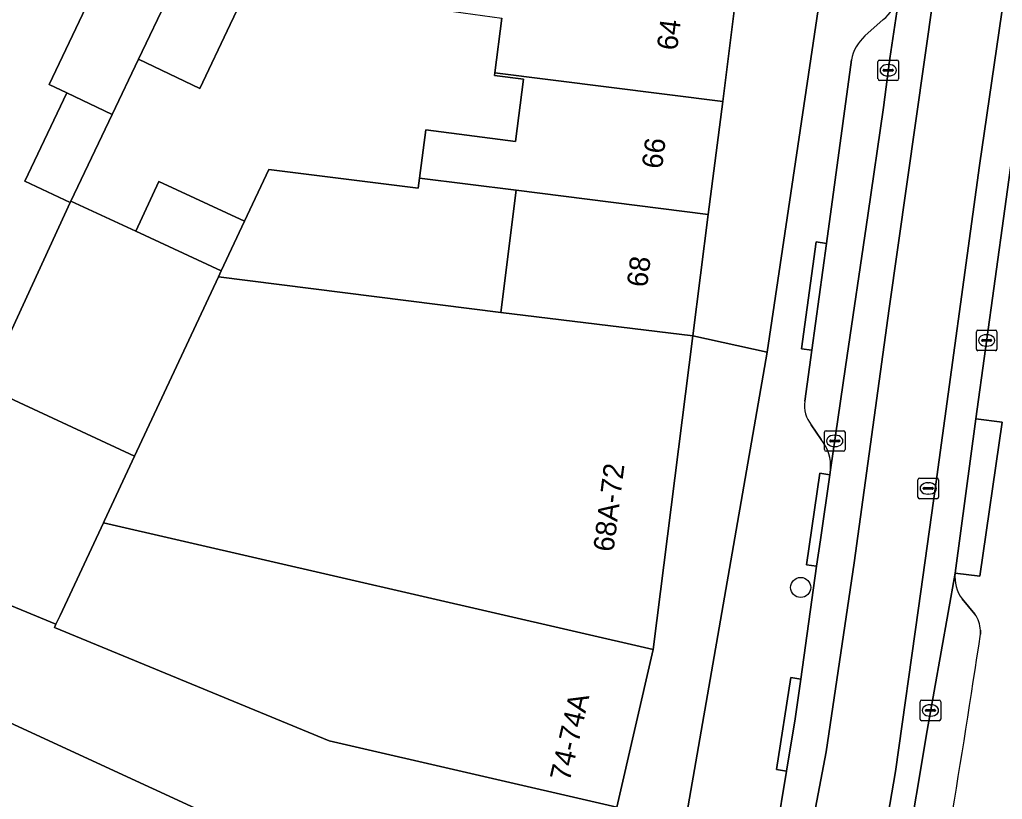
# Model space of a CAD drawing. Extents: x 160349 to 161355, y 381727 to 382854.
# Drawn here: x 160838.74 to 160886.69, y 382389.67 to 382427.71 of the extents above; entities that cross this region are included whole.
import ezdxf

# ---------------------------------------------------------------- set-up
doc = ezdxf.new("R2010")
doc.units = 0
for name, color, linetype in [('IMGEO_Boom', 7, 'Continuous'), ('IMGEO_Erf', 7, 'Continuous'), ('IMGEO_Kolk', 7, 'Continuous'), ('IMGEO_Pand', 7, 'Continuous'), ('IMGEO_Pand_nummerreeks', 7, 'Continuous'), ('IMGEO_Parkeervlak_open', 7, 'Continuous'), ('IMGEO_Rijbaan_lokaal_gesloten', 7, 'Continuous'), ('IMGEO_Rioolput', 7, 'Continuous'), ('IMGEO_Voetpad_open', 7, 'Continuous')]:
    doc.layers.add(name, color=color, linetype=linetype)

msp = doc.modelspace()

# ---------------------------------------------------------------- linework, layer by layer
at = {"layer": 'IMGEO_Boom'}
msp.add_circle((160876.853, 382400.008), 0.489, dxfattribs=at)
at = {"layer": 'IMGEO_Erf'}
for points in [[(160838.99, 382419.837), (160841.034, 382424.136), (160840.178, 382424.543), (160844.715, 382434.085), (160840.65, 382435.888), (160842.793, 382440.716), (160844.328, 382440.034), (160845.356, 382442.352), (160847.503, 382446.867), (160844.97, 382447.935), (160842.8, 382443.431), (160841.079, 382439.861), (160841.402, 382439.699), (160836.819, 382430.561)], [(160850.819, 382431.268), (160849.014, 382427.472), (160847.534, 382424.359), (160844.542, 382425.78), (160843.259, 382423.078), (160841.24, 382418.852), (160844.41, 382417.386), (160845.531, 382419.811), (160849.711, 382417.879), (160850.893, 382420.407), (160858.191, 382419.481), (160858.255, 382419.983), (160858.552, 382422.327), (160862.934, 382421.771), (160863.319, 382424.806), (160861.918, 382424.983), (160861.935, 382425.121), (160862.273, 382427.785)], [(160833.248, 382401.214), (160840.51, 382398.208), (160840.713, 382398.638), (160842.823, 382403.154), (160842.875, 382403.269), (160844.341, 382406.407), (160837.05, 382409.79), (160841.207, 382418.783), (160838.99, 382419.837)], [(160852.386, 382386.901), (160831.107, 382396.697), (160827.103, 382388.219)]]:
    msp.add_lwpolyline(points, dxfattribs=at)
at = {"layer": 'IMGEO_Kolk'}
for p, q in [((160880.626, 382424.815), (160880.626, 382425.667)), ((160880.701, 382425.741), (160881.553, 382425.741)), ((160881.114, 382425.521), (160881.139, 382425.521)), ((160881.627, 382425.667), (160881.627, 382424.815)), ((160880.885, 382425.235), (160880.885, 382425.247)), ((160881.323, 382425.198), (160880.925, 382425.198)), ((160880.928, 382425.284), (160881.326, 382425.284)), ((160881.369, 382425.247), (160881.369, 382425.235)), ((160881.553, 382424.741), (160880.701, 382424.741)), ((160881.137, 382424.961), (160881.112, 382424.961)), ((160885.503, 382412.56), (160886.355, 382412.56)), ((160885.428, 382411.634), (160885.428, 382412.486)), ((160885.687, 382412.054), (160885.687, 382412.066)), ((160885.73, 382412.103), (160886.128, 382412.103)), ((160885.916, 382412.34), (160885.941, 382412.34)), ((160886.171, 382412.066), (160886.171, 382412.054)), ((160886.429, 382412.486), (160886.429, 382411.634)), ((160886.355, 382411.56), (160885.503, 382411.56)), ((160886.125, 382412.017), (160885.727, 382412.017)), ((160885.939, 382411.78), (160885.914, 382411.78)), ((160878.015, 382406.73), (160878.015, 382407.582)), ((160878.09, 382407.656), (160878.942, 382407.656)), ((160878.503, 382407.436), (160878.528, 382407.436)), ((160879.016, 382407.582), (160879.016, 382406.73)), ((160878.274, 382407.15), (160878.274, 382407.162)), ((160878.712, 382407.113), (160878.314, 382407.113)), ((160878.317, 382407.199), (160878.715, 382407.199)), ((160878.526, 382406.876), (160878.501, 382406.876)), ((160878.758, 382407.162), (160878.758, 382407.15)), ((160878.942, 382406.656), (160878.09, 382406.656)), ((160882.684, 382393.58), (160882.684, 382394.432)), ((160882.759, 382394.506), (160883.611, 382394.506)), ((160883.172, 382394.286), (160883.197, 382394.286)), ((160883.685, 382394.432), (160883.685, 382393.58)), ((160882.943, 382394), (160882.943, 382394.012)), ((160883.381, 382393.963), (160882.983, 382393.963)), ((160882.986, 382394.049), (160883.384, 382394.049)), ((160883.427, 382394.012), (160883.427, 382394)), ((160883.611, 382393.506), (160882.759, 382393.506)), ((160883.195, 382393.726), (160883.17, 382393.726))]:
    msp.add_line(p, q, dxfattribs=at)
for points in [[(160880.626, 382424.815), (160880.626, 382425.667)], [(160880.701, 382425.741), (160881.553, 382425.741)], [(160881.627, 382425.667), (160881.627, 382424.815)], [(160881.553, 382424.741), (160880.701, 382424.741)], [(160885.503, 382412.56), (160886.355, 382412.56)], [(160885.428, 382411.634), (160885.428, 382412.486)], [(160886.429, 382412.486), (160886.429, 382411.634)], [(160886.355, 382411.56), (160885.503, 382411.56)], [(160878.015, 382406.73), (160878.015, 382407.582)], [(160878.09, 382407.656), (160878.942, 382407.656)], [(160879.016, 382407.582), (160879.016, 382406.73)], [(160878.942, 382406.656), (160878.09, 382406.656)], [(160882.684, 382393.58), (160882.684, 382394.432)], [(160882.759, 382394.506), (160883.611, 382394.506)], [(160883.685, 382394.432), (160883.685, 382393.58)], [(160883.611, 382393.506), (160882.759, 382393.506)]]:
    msp.add_lwpolyline(points, dxfattribs=at)
for centre, radius, start, end in [((160880.703, 382425.665), 0.0765, 91.552, 178.448), ((160880.703, 382425.665), 0.0765, 91.552, 178.448), ((160881.551, 382425.665), 0.0765, 1.552, 88.448), ((160881.551, 382425.665), 0.0765, 1.552, 88.448), ((160880.925, 382425.244), 0.0403, 85.8775, 175.7526), ((160880.922, 382425.234), 0.0366, 178.938, 274.7102), ((160881.326, 382425.241), 0.043, 264.8664, 352.4533), ((160881.33, 382425.246), 0.0386, 1.7309, 96.639), ((160880.703, 382424.817), 0.0765, 181.552, 268.448), ((160880.703, 382424.817), 0.0765, 181.552, 268.448), ((160881.551, 382424.817), 0.0765, 271.552, 358.448), ((160881.551, 382424.817), 0.0765, 271.552, 358.448), ((160885.505, 382412.484), 0.0765, 91.552, 178.448), ((160885.505, 382412.484), 0.0765, 91.552, 178.448), ((160886.353, 382412.484), 0.0765, 1.552, 88.448), ((160886.353, 382412.484), 0.0765, 1.552, 88.448), ((160885.727, 382412.063), 0.0403, 85.8775, 175.7526), ((160885.724, 382412.053), 0.0366, 178.938, 274.7102), ((160886.128, 382412.06), 0.043, 264.8664, 352.4533), ((160886.132, 382412.065), 0.0386, 1.7309, 96.639), ((160885.505, 382411.636), 0.0765, 181.552, 268.448), ((160885.505, 382411.636), 0.0765, 181.552, 268.448), ((160886.353, 382411.636), 0.0765, 271.552, 358.448), ((160886.353, 382411.636), 0.0765, 271.552, 358.448), ((160878.092, 382407.58), 0.0765, 91.552, 178.448), ((160878.092, 382407.58), 0.0765, 91.552, 178.448), ((160878.94, 382407.58), 0.0765, 1.552, 88.448), ((160878.94, 382407.58), 0.0765, 1.552, 88.448), ((160878.314, 382407.159), 0.0403, 85.8775, 175.7526), ((160878.311, 382407.149), 0.0366, 178.938, 274.7102), ((160878.715, 382407.156), 0.043, 264.8664, 352.4533), ((160878.719, 382407.161), 0.0386, 1.7309, 96.639), ((160878.092, 382406.732), 0.0765, 181.552, 268.448), ((160878.092, 382406.732), 0.0765, 181.552, 268.448), ((160878.94, 382406.732), 0.0765, 271.552, 358.448), ((160878.94, 382406.732), 0.0765, 271.552, 358.448), ((160882.761, 382394.43), 0.0765, 91.552, 178.448), ((160882.761, 382394.43), 0.0765, 91.552, 178.448), ((160883.609, 382394.43), 0.0765, 1.552, 88.448), ((160883.609, 382394.43), 0.0765, 1.552, 88.448), ((160882.983, 382394.009), 0.0403, 85.8775, 175.7526), ((160882.98, 382393.999), 0.0366, 178.938, 274.7102), ((160883.384, 382394.006), 0.043, 264.8664, 352.4533), ((160883.388, 382394.011), 0.0386, 1.7309, 96.639), ((160882.761, 382393.582), 0.0765, 181.552, 268.448), ((160882.761, 382393.582), 0.0765, 181.552, 268.448), ((160883.609, 382393.582), 0.0765, 271.552, 358.448), ((160883.609, 382393.582), 0.0765, 271.552, 358.448)]:
    msp.add_arc(centre, radius, start, end, dxfattribs=at)
for centre, major_axis, ratio, start_param, end_param in [((160881.113, 382425.241), (-0.387, 0.002), 0.722429, 4.712389, 7.853982), ((160881.138, 382425.241), (-0.39, 0.002), 0.717154, 1.570796, 4.712389), ((160885.915, 382412.06), (-0.387, 0.002), 0.722429, 4.712389, 7.853982), ((160885.94, 382412.06), (-0.39, 0.002), 0.717154, 1.570796, 4.712389), ((160878.502, 382407.156), (-0.387, 0.002), 0.722429, 4.712389, 7.853982), ((160878.527, 382407.156), (-0.39, 0.002), 0.717154, 1.570796, 4.712389), ((160883.171, 382394.006), (-0.387, 0.002), 0.722429, 4.712389, 7.853982), ((160883.196, 382394.006), (-0.39, 0.002), 0.717154, 1.570796, 4.712389)]:
    msp.add_ellipse(centre, major_axis=major_axis, ratio=ratio, start_param=start_param, end_param=end_param, dxfattribs=at)
at = {"layer": 'IMGEO_Pand'}
for points in [[(160853.11, 382443.819), (160850.234, 382445.187), (160850.382, 382445.498), (160847.503, 382446.867), (160845.356, 382442.352), (160844.328, 382440.034), (160842.793, 382440.716), (160840.65, 382435.888), (160844.715, 382434.085), (160840.178, 382424.543), (160841.034, 382424.136), (160843.259, 382423.078), (160844.542, 382425.78), (160846.022, 382428.895)], [(160857.557, 382436.557), (160859.705, 382441.072), (160854.36, 382443.615), (160854.209, 382443.296), (160853.11, 382443.819), (160846.022, 382428.895), (160844.542, 382425.78), (160847.534, 382424.359), (160849.014, 382427.472), (160850.819, 382431.268), (160855.018, 382429.271), (160856.844, 382433.112), (160856.069, 382433.471)], [(160873.776, 382429.466), (160857.365, 382431.653), (160856.39, 382429.554), (160858.62, 382429.248), (160858.489, 382428.298), (160862.273, 382427.785), (160861.935, 382425.121), (160873.046, 382423.712)], [(160861.935, 382425.121), (160861.918, 382424.983), (160863.319, 382424.806), (160862.934, 382421.771), (160858.552, 382422.327), (160858.255, 382419.983), (160862.976, 382419.385), (160872.346, 382418.197), (160873.046, 382423.712)], [(160843.259, 382423.078), (160841.034, 382424.136), (160838.99, 382419.837), (160841.207, 382418.783), (160841.24, 382418.852)], [(160848.579, 382415.459), (160848.442, 382415.167), (160862.22, 382413.42), (160862.976, 382419.385), (160858.255, 382419.983), (160858.191, 382419.481), (160850.893, 382420.407), (160849.711, 382417.879)], [(160848.579, 382415.459), (160849.711, 382417.879), (160845.531, 382419.811), (160844.41, 382417.386)], [(160872.346, 382418.197), (160862.976, 382419.385), (160862.22, 382413.42), (160871.595, 382412.277)], [(160848.442, 382415.167), (160848.579, 382415.459), (160844.41, 382417.386), (160841.24, 382418.852), (160841.207, 382418.783), (160837.05, 382409.79), (160844.341, 382406.407)], [(160844.341, 382406.407), (160842.875, 382403.269), (160842.823, 382403.154), (160869.655, 382396.98), (160871.595, 382412.277), (160862.22, 382413.42), (160848.442, 382415.167)], [(160842.823, 382403.154), (160840.713, 382398.638), (160840.51, 382398.208), (160840.441, 382398.06), (160853.85, 382392.531), (160867.882, 382389.295), (160869.655, 382396.98)], [(160857.877, 382385.543), (160866.575, 382383.629), (160867.882, 382389.295), (160853.85, 382392.531), (160840.441, 382398.06), (160840.51, 382398.208), (160833.248, 382401.214), (160831.107, 382396.697), (160852.386, 382386.901), (160856.493, 382385.863)]]:
    msp.add_lwpolyline(points, close=True, dxfattribs=at)
at = {"layer": 'IMGEO_Parkeervlak_open'}
for points in [[(160878.312, 382405.748), (160879.045, 382410.779), (160880.13, 382418.151), (160880.898, 382423.426), (160881.202, 382425.818), (160881.647, 382428.757)], [(160880.886, 382427.71), (160879.99, 382426.916)], [(160879.326, 382425.742), (160878.106, 382416.795), (160877.395, 382411.585), (160877.055, 382409.091)], [(160877.369, 382407.938), (160877.857, 382407.231)], [(160884.389, 382400.707), (160883.026, 382393.026), (160880.919, 382380.402), (160878.135, 382368.511), (160876.154, 382361.855), (160875.162, 382358.523), (160869.629, 382343.884)], [(160885.353, 382398.704), (160884.727, 382399.448)], [(160885.633, 382397.726), (160885.626, 382397.917)]]:
    msp.add_lwpolyline(points, dxfattribs=at)
for centre, radius, start, end in [((160878.953, 382429.915), 2.932, 311.2385, 336.7393), ((160881.385, 382425.353), 2.095, 131.7305, 169.2856), ((160878.526, 382408.872), 1.487, 171.5487, 218.9195), ((160876.137, 382405.892), 2.18, 356.2113, 37.9018), ((160886.232, 382400.527), 1.851, 174.4143, 215.641), ((160884.197, 382397.862), 1.43, 2.2007, 36.0612), ((160242.151, 382494.956), 650.786, 349.758294, 351.407572)]:
    msp.add_arc(centre, radius, start, end, dxfattribs=at)
at = {"layer": 'IMGEO_Rijbaan_lokaal_gesloten'}
for points in [[(160885.854, 382456.356), (160885.223, 382452.521), (160884.594, 382448.404), (160881.688, 382429.028), (160881.647, 382428.757), (160881.202, 382425.818), (160880.898, 382423.426), (160880.13, 382418.151), (160879.045, 382410.779), (160878.312, 382405.748), (160878.277, 382405.504), (160877.814, 382402.326), (160877.633, 382401.041), (160876.858, 382395.532), (160876.585, 382393.594), (160876.163, 382391.049), (160875.148, 382384.925), (160874.712, 382382.293), (160873.06, 382374.355)], [(160870.943, 382366.742), (160870.039, 382363.675), (160871.535, 382363.229), (160871.549, 382363.225), (160872.864, 382367.516), (160875.093, 382376.203), (160878.093, 382391.995), (160879.468, 382401.203), (160881.177, 382413.62), (160883.781, 382431.953), (160885.906, 382445.891), (160887.065, 382452.22)], [(160887.065, 382452.22), (160885.906, 382445.891), (160883.781, 382431.953), (160881.177, 382413.62), (160879.468, 382401.203), (160878.093, 382391.995), (160875.093, 382376.203), (160872.864, 382367.516), (160871.549, 382363.225), (160874.812, 382362.252), (160876.305, 382367.268), (160878.01, 382373.759), (160879.223, 382378.677), (160880.076, 382382.874), (160881.485, 382391.022), (160882.6, 382398.989), (160883.453, 382405.054), (160885.584, 382420.595), (160889.059, 382444.497), (160890.141, 382451.415)], [(160889.059, 382444.497), (160885.584, 382420.595), (160883.453, 382405.054), (160882.6, 382398.989), (160881.485, 382391.022), (160880.076, 382382.874), (160879.223, 382378.677), (160878.01, 382373.759), (160876.305, 382367.268), (160874.812, 382362.252), (160876.154, 382361.855), (160878.135, 382368.511), (160880.919, 382380.402), (160883.026, 382393.026), (160884.389, 382400.707), (160885.402, 382408.232), (160887.753, 382425.309)]]:
    msp.add_lwpolyline(points, dxfattribs=at)
at = {"layer": 'IMGEO_Rioolput'}
for p, q in [((160882.652, 382405.338), (160883.504, 382405.338)), ((160882.577, 382404.412), (160882.577, 382405.264)), ((160882.836, 382404.832), (160882.836, 382404.844)), ((160882.879, 382404.881), (160883.277, 382404.881)), ((160883.065, 382405.118), (160883.09, 382405.118)), ((160883.32, 382404.844), (160883.32, 382404.832)), ((160883.578, 382405.264), (160883.578, 382404.412)), ((160883.274, 382404.795), (160882.876, 382404.795)), ((160883.088, 382404.558), (160883.063, 382404.558)), ((160883.504, 382404.338), (160882.652, 382404.338))]:
    msp.add_line(p, q, dxfattribs=at)
for points in [[(160882.652, 382405.338), (160883.504, 382405.338)], [(160882.577, 382404.412), (160882.577, 382405.264)], [(160883.578, 382405.264), (160883.578, 382404.412)], [(160883.504, 382404.338), (160882.652, 382404.338)]]:
    msp.add_lwpolyline(points, dxfattribs=at)
for centre, radius, start, end in [((160882.654, 382405.262), 0.0765, 91.552, 178.448), ((160882.654, 382405.262), 0.0765, 91.552, 178.448), ((160883.502, 382405.262), 0.0765, 1.552, 88.448), ((160883.502, 382405.262), 0.0765, 1.552, 88.448), ((160882.876, 382404.841), 0.0403, 85.8775, 175.7526), ((160883.281, 382404.843), 0.0386, 1.7309, 96.639), ((160882.654, 382404.414), 0.0765, 181.552, 268.448), ((160882.654, 382404.414), 0.0765, 181.552, 268.448), ((160882.873, 382404.831), 0.0366, 178.938, 274.7102), ((160883.277, 382404.838), 0.043, 264.8664, 352.4533), ((160883.502, 382404.414), 0.0765, 271.552, 358.448), ((160883.502, 382404.414), 0.0765, 271.552, 358.448)]:
    msp.add_arc(centre, radius, start, end, dxfattribs=at)
for centre, major_axis, ratio, start_param, end_param in [((160883.064, 382404.838), (-0.387, 0.002), 0.722429, 4.712389, 7.853982), ((160883.089, 382404.838), (-0.39, 0.002), 0.717154, 1.570796, 4.712389)]:
    msp.add_ellipse(centre, major_axis=major_axis, ratio=ratio, start_param=start_param, end_param=end_param, dxfattribs=at)
at = {"layer": 'IMGEO_Voetpad_open'}
for points in [[(160877.876, 382429.319), (160878.34, 382432.421), (160874.377, 382434.208), (160874.342, 382433.93), (160877.67, 382432.369), (160877.181, 382428.975), (160873.776, 382429.466), (160873.046, 382423.712), (160872.346, 382418.197), (160871.595, 382412.277), (160875.211, 382411.49)], [(160878.106, 382416.795), (160877.612, 382416.866), (160876.901, 382411.656), (160877.395, 382411.585)], [(160875.211, 382411.49), (160871.595, 382412.277), (160869.655, 382396.98), (160867.882, 382389.295), (160866.575, 382383.629), (160870.226, 382382.815)], [(160884.389, 382400.707), (160885.595, 382400.556), (160886.686, 382408.076), (160885.402, 382408.232)], [(160878.277, 382405.504), (160877.783, 382405.578), (160877.139, 382401.115), (160877.633, 382401.041), (160877.814, 382402.326)], [(160876.858, 382395.532), (160876.365, 382395.612), (160875.67, 382391.129), (160876.163, 382391.049), (160876.585, 382393.594)]]:
    msp.add_lwpolyline(points, close=True, dxfattribs=at)
for points in [[(160888.323, 382429.899), (160888.221, 382429.209), (160887.753, 382425.309), (160885.402, 382408.232), (160886.686, 382408.076), (160885.595, 382400.556), (160884.389, 382400.707)], [(160881.647, 382428.757), (160877.876, 382429.319), (160875.211, 382411.49), (160870.226, 382382.815), (160869.032, 382377.343), (160867.643, 382370.512), (160865.485, 382363.027), (160864.432, 382359.377)], [(160879.99, 382426.916), (160880.886, 382427.71)], [(160877.055, 382409.091), (160877.395, 382411.585), (160876.901, 382411.656), (160877.612, 382416.866), (160878.106, 382416.795), (160879.326, 382425.742)], [(160877.857, 382407.231), (160877.369, 382407.938)], [(160873.06, 382374.355), (160874.712, 382382.293), (160875.148, 382384.925), (160876.163, 382391.049), (160875.67, 382391.129), (160876.365, 382395.612), (160876.858, 382395.532), (160877.633, 382401.041), (160877.139, 382401.115), (160877.783, 382405.578), (160878.277, 382405.504), (160878.312, 382405.748)], [(160884.727, 382399.448), (160885.353, 382398.704)], [(160885.626, 382397.917), (160885.633, 382397.726)]]:
    msp.add_lwpolyline(points, dxfattribs=at)
for centre, radius, start, end in [((160878.953, 382429.915), 2.932, 311.2385, 336.7393), ((160881.385, 382425.353), 2.095, 131.7305, 169.2856), ((160878.526, 382408.872), 1.487, 171.5487, 218.9195), ((160876.137, 382405.892), 2.18, 356.2113, 37.9018), ((160886.232, 382400.527), 1.851, 174.4143, 215.641), ((160884.197, 382397.862), 1.43, 2.2007, 36.0612), ((160242.151, 382494.956), 650.786, 349.758294, 351.407572)]:
    msp.add_arc(centre, radius, start, end, dxfattribs=at)

# ---------------------------------------------------------------- texts
at = {"layer": 'IMGEO_Pand_nummerreeks'}
for s, rotation, p in [('64', 82.7695, (160870.818, 382426.178)), ('66', 82.7716, (160870.085, 382420.399)), ('68', 82.7716, (160869.353, 382414.623)), ('68A-72', 82.7722, (160867.715, 382401.712)), ('74-74A', 77.0087, (160865.576, 382390.509))]:
    msp.add_text(s, height=1, rotation=rotation, dxfattribs=at).set_placement(p)

doc.saveas('drawing.dxf')
